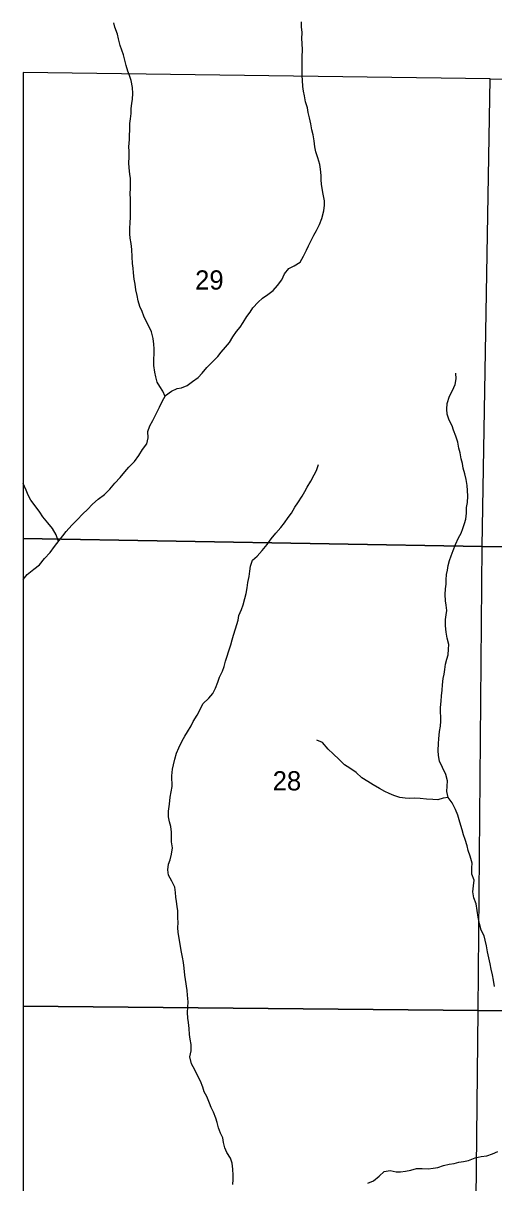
# Model space of a CAD drawing. Extents: x -10 to 158, y 8 to 33.
# Drawn here: x 24.6 to 25.627, y 16.093 to 18.62 of the extents above; entities that cross this region are included whole.
import ezdxf

# ---------------------------------------------------------------- set-up
doc = ezdxf.new("R2010")
doc.units = 0
for name, color, linetype in [('GM_X_Corporation', 7, 'Continuous'), ('GM_X_Minor_River', 7, 'Continuous'), ('GM_X_Section_Text', 7, 'Continuous')]:
    doc.layers.add(name, color=color, linetype=linetype)

msp = doc.modelspace()

# ---------------------------------------------------------------- linework, layer by layer
at = {"layer": 'GM_X_Corporation'}
for points in [[(24.6, 18.5128), (24.6, 17.4969), (25.6011, 17.4797), (25.6188, 18.4989)], [(25.6188, 18.4989), (26.6319, 18.4884), (26.6176, 17.4733), (25.6011, 17.4797)], [(24.6, 17.4969), (24.6, 16.4774), (25.5928, 16.4681), (25.6011, 17.4797)], [(25.6011, 17.4797), (26.6176, 17.4733), (26.6025, 16.4586), (25.5928, 16.4681)], [(24.6, 16.4774), (24.6, 15.4569), (25.5813, 15.4398), (25.5928, 16.4681)], [(26.6025, 16.4586), (26.5887, 15.4288), (25.5813, 15.4398), (25.5928, 16.4681)]]:
    msp.add_lwpolyline(points, close=True, dxfattribs=at)
at = {"layer": 'GM_X_Minor_River'}
for points in [[(24.9097, 17.8068), (24.9044, 17.8182), (24.8979, 17.828), (24.8926, 17.8379), (24.8891, 17.8497), (24.8872, 17.8595), (24.8853, 17.874), (24.8848, 17.8865), (24.8859, 17.9013), (24.8859, 17.9108), (24.8851, 17.9203), (24.8832, 17.9332), (24.8798, 17.9476), (24.8748, 17.9586), (24.8679, 17.9719), (24.863, 17.9818), (24.8595, 17.992), (24.8546, 18.0026), (24.8508, 18.0152), (24.8484, 18.0269), (24.8461, 18.0391), (24.8442, 18.0516), (24.8423, 18.0626), (24.8407, 18.0759), (24.8396, 18.0865), (24.8388, 18.0968), (24.838, 18.1112), (24.8372, 18.1272), (24.8356, 18.1401), (24.8333, 18.1515), (24.8325, 18.1613), (24.8325, 18.1739), (24.8336, 18.1845), (24.834, 18.1982), (24.8343, 18.213), (24.8343, 18.2248), (24.8339, 18.2362), (24.8335, 18.2499), (24.8338, 18.2594), (24.8342, 18.2715), (24.8338, 18.2814), (24.8326, 18.2913), (24.831, 18.3049), (24.8306, 18.3156), (24.831, 18.3285), (24.831, 18.341), (24.8306, 18.3509), (24.8317, 18.3665), (24.832, 18.3764), (24.8324, 18.387), (24.8327, 18.4014), (24.8342, 18.4121), (24.8353, 18.4235), (24.8357, 18.4341), (24.8368, 18.4451), (24.8383, 18.4546), (24.8394, 18.4672), (24.8386, 18.4801), (24.8355, 18.4953), (24.8321, 18.5059), (24.8282, 18.5154), (24.8248, 18.5283), (24.8221, 18.5397), (24.8187, 18.551), (24.8149, 18.5613), (24.8114, 18.5719), (24.8083, 18.5863), (24.8057, 18.5966), (24.8003, 18.6114), (24.7976, 18.6209)], [(25.1338, 18.029), (25.1452, 18.0378), (25.155, 18.0488), (25.1644, 18.061), (25.1701, 18.0736), (25.1792, 18.0858), (25.1913, 18.0915), (25.2042, 18.0995), (25.2118, 18.1125), (25.2178, 18.1258), (25.2223, 18.1353), (25.2284, 18.1463), (25.2344, 18.1585), (25.2401, 18.1684), (25.2465, 18.1817), (25.2518, 18.1947), (25.2559, 18.211), (25.2574, 18.2239), (25.257, 18.2334), (25.2543, 18.2475), (25.252, 18.2596), (25.2508, 18.2691), (25.25, 18.2786), (25.25, 18.2885), (25.2488, 18.3018), (25.2469, 18.312), (25.2431, 18.3265), (25.2385, 18.3401), (25.2362, 18.3511), (25.235, 18.364), (25.2327, 18.3766), (25.2297, 18.3876), (25.2273, 18.4012), (25.2247, 18.4141), (25.2216, 18.4259), (25.2204, 18.4358), (25.2162, 18.4487), (25.2135, 18.462), (25.2112, 18.4722), (25.2097, 18.4821), (25.2093, 18.4961), (25.2089, 18.5056), (25.2088, 18.5337), (25.2084, 18.5478), (25.2091, 18.5615), (25.2087, 18.577), (25.2075, 18.5865), (25.2086, 18.6002), (25.2071, 18.6124), (25.2074, 18.623)], [(24.6, 17.408), (24.609, 17.4183), (24.623, 17.4305), (24.6359, 17.4393), (24.6465, 17.4534), (24.6586, 17.4667), (24.6684, 17.4793), (24.6787, 17.4926), (24.6866, 17.5029), (24.6938, 17.5124), (24.7059, 17.5262), (24.718, 17.538), (24.7305, 17.5505), (24.7403, 17.5601), (24.7513, 17.5719), (24.7634, 17.5826), (24.7771, 17.5932), (24.7888, 17.6047), (24.8001, 17.6173), (24.8115, 17.6302), (24.8217, 17.642), (24.8308, 17.6527), (24.8425, 17.6645), (24.852, 17.6778), (24.8603, 17.6912), (24.8698, 17.7033), (24.8724, 17.7166), (24.872, 17.7299), (24.8761, 17.7429), (24.8829, 17.7539), (24.8897, 17.7676), (24.8973, 17.7836), (24.9029, 17.7958), (24.9108, 17.8087), (24.9237, 17.8179), (24.9362, 17.824), (24.9457, 17.8252), (24.9575, 17.8305), (24.9692, 17.8393), (24.9817, 17.8477), (24.9904, 17.8572), (25.0006, 17.8698), (25.0249, 17.8934), (25.0317, 17.9029), (25.0411, 17.914), (25.0502, 17.9243), (25.0574, 17.9365), (25.0653, 17.9479), (25.0733, 17.9578), (25.0801, 17.9681), (25.088, 17.981), (25.0948, 17.9905), (25.1012, 18), (25.1126, 18.0119), (25.1224, 18.0206), (25.1338, 18.029)], [(25.5224, 17.3975), (25.5228, 17.407), (25.5235, 17.4184), (25.5254, 17.4279), (25.5272, 17.4382), (25.5299, 17.4492), (25.5336, 17.4591), (25.5378, 17.4712), (25.5434, 17.4842), (25.5499, 17.4986), (25.5555, 17.5089), (25.5593, 17.5188), (25.5627, 17.5294), (25.5657, 17.5393), (25.5672, 17.5519), (25.5672, 17.5648), (25.5694, 17.5758), (25.5701, 17.5891), (25.569, 17.602), (25.5686, 17.6126), (25.5666, 17.6255), (25.5632, 17.6381), (25.5601, 17.6502), (25.5582, 17.6605), (25.5555, 17.6707), (25.5536, 17.684), (25.5505, 17.6939), (25.5478, 17.7071), (25.544, 17.7204), (25.5387, 17.7329), (25.5356, 17.7424), (25.5291, 17.7546), (25.5249, 17.7682), (25.5245, 17.7789), (25.5249, 17.7914), (25.5301, 17.807), (25.5362, 17.8199), (25.5422, 17.8325), (25.5448, 17.845), (25.544, 17.8576)], [(24.971, 17.0982), (24.9797, 17.1119), (24.9865, 17.126), (24.9918, 17.1363), (25.0047, 17.1489), (25.0138, 17.1592), (25.0198, 17.171), (25.0243, 17.1839), (25.0285, 17.1945), (25.0349, 17.2075), (25.0387, 17.2181), (25.0417, 17.2295), (25.0447, 17.2402), (25.0481, 17.25), (25.053, 17.2649), (25.0556, 17.2759), (25.0586, 17.2865), (25.0631, 17.2998), (25.0661, 17.3094), (25.0688, 17.3189), (25.0706, 17.3291), (25.0759, 17.3421), (25.0797, 17.3527), (25.0835, 17.3664), (25.0865, 17.377), (25.0887, 17.3896), (25.0902, 17.401), (25.0928, 17.4139), (25.0943, 17.4257), (25.0958, 17.4367), (25.0999, 17.4496), (25.1102, 17.4584), (25.1215, 17.471), (25.1321, 17.4843), (25.1412, 17.4965), (25.1514, 17.509), (25.1624, 17.5212), (25.1699, 17.5311), (25.1783, 17.5429), (25.1851, 17.5525), (25.1923, 17.565), (25.1991, 17.5745), (25.2085, 17.589), (25.2142, 17.5997), (25.2198, 17.6092), (25.2274, 17.6221), (25.235, 17.6358), (25.2395, 17.6453), (25.2444, 17.6583)], [(24.6772, 17.4908), (24.6718, 17.5051), (24.6642, 17.5188), (24.6535, 17.5313), (24.6432, 17.5446), (24.6364, 17.5544), (24.6265, 17.568), (24.6166, 17.5806), (24.6112, 17.5912), (24.6067, 17.6025), (24.6002, 17.6166), (24.6, 17.6169)], [(25.6281, 16.5206), (25.6258, 16.5343), (25.6235, 16.5457), (25.6208, 16.5582), (25.6189, 16.5696), (25.6158, 16.5829), (25.6131, 16.5958), (25.6104, 16.609), (25.6081, 16.6216), (25.6054, 16.631), (25.5993, 16.6432), (25.5951, 16.6568), (25.5924, 16.6713), (25.5905, 16.6864), (25.5878, 16.7005), (25.5832, 16.7141), (25.5809, 16.7266), (25.5824, 16.7396), (25.5839, 16.7525), (25.5786, 16.765), (25.5785, 16.779), (25.5793, 16.7893), (25.5754, 16.8045), (25.5709, 16.817), (25.5682, 16.8269), (25.564, 16.8409), (25.5605, 16.8511), (25.5578, 16.8618), (25.5548, 16.8716), (25.551, 16.8838), (25.5479, 16.894), (25.5433, 16.9065), (25.5357, 16.9205), (25.5273, 16.9323), (25.5243, 16.9452), (25.525, 16.957), (25.5253, 16.9691), (25.5219, 16.9828), (25.5146, 16.9979), (25.5085, 17.012), (25.5059, 17.0241), (25.5055, 17.0347), (25.5062, 17.0499), (25.5065, 17.0606), (25.508, 17.0765), (25.5103, 17.0883), (25.5114, 17.0989), (25.511, 17.1084), (25.5102, 17.1187), (25.5105, 17.1289), (25.5116, 17.1426), (25.5124, 17.1544), (25.5142, 17.1666), (25.515, 17.1783), (25.5165, 17.1916), (25.518, 17.2015), (25.5198, 17.2118), (25.5213, 17.2228), (25.5239, 17.2338), (25.527, 17.2433), (25.5281, 17.2555), (25.5288, 17.2657), (25.525, 17.2801), (25.523, 17.2931), (25.5215, 17.3067), (25.5215, 17.3208), (25.5226, 17.3303), (25.5241, 17.3398), (25.5225, 17.3519), (25.5214, 17.3614), (25.5206, 17.3751), (25.5213, 17.3876), (25.5224, 17.3975)], [(25.0576, 16.0889), (25.058, 16.0995), (25.0579, 16.109), (25.0575, 16.1223), (25.0556, 16.1352), (25.0525, 16.1462), (25.0442, 16.1587), (25.04, 16.1686), (25.0373, 16.1803), (25.0354, 16.1906), (25.0304, 16.2008), (25.0258, 16.2122), (25.0231, 16.2243), (25.0205, 16.2338), (25.0151, 16.2467), (25.0098, 16.2566), (25.0064, 16.2664), (25.0003, 16.2808), (24.9949, 16.291), (24.9919, 16.3013), (24.9865, 16.3138), (24.9785, 16.3297), (24.9743, 16.3392), (24.9671, 16.3521), (24.9636, 16.3673), (24.9663, 16.3806), (24.9662, 16.3938), (24.9643, 16.406), (24.9628, 16.4162), (24.962, 16.4288), (24.9604, 16.4417), (24.9593, 16.4512), (24.9585, 16.4637), (24.9592, 16.4758), (24.9596, 16.4872), (24.9588, 16.5013), (24.9576, 16.5119), (24.9541, 16.5358), (24.953, 16.5453), (24.9514, 16.5601), (24.9495, 16.573), (24.9472, 16.5844), (24.9449, 16.5988), (24.9426, 16.6128), (24.9406, 16.6254), (24.9383, 16.6386), (24.9376, 16.6485), (24.9379, 16.6599), (24.9375, 16.6705), (24.9371, 16.6853), (24.9359, 16.6948), (24.9344, 16.7058), (24.9329, 16.7153), (24.9321, 16.7256), (24.9305, 16.737), (24.9244, 16.7499), (24.9172, 16.7635), (24.9156, 16.7749), (24.9167, 16.787), (24.9205, 16.7969), (24.9235, 16.8091), (24.9254, 16.8228), (24.9238, 16.8357), (24.9238, 16.8459), (24.9234, 16.8569), (24.9219, 16.8695), (24.9192, 16.8793), (24.9173, 16.89), (24.9169, 16.9029), (24.9195, 16.9181), (24.921, 16.9329), (24.9228, 16.9447), (24.9247, 16.9564), (24.9246, 16.98), (24.9257, 16.994), (24.928, 17.0035), (24.9306, 17.0157), (24.9344, 17.029), (24.9397, 17.0404), (24.9468, 17.056), (24.9525, 17.0663), (24.9582, 17.0758), (24.9665, 17.0887), (24.971, 17.0982)], [(25.5273, 16.9323), (25.5163, 16.9311), (25.5042, 16.9273), (25.4939, 16.928), (25.4795, 16.9287), (25.4659, 16.9306), (25.453, 16.9309), (25.4431, 16.9305), (25.4336, 16.9312), (25.4215, 16.9327), (25.4085, 16.9368), (25.3987, 16.941), (25.3888, 16.9459), (25.3774, 16.9519), (25.3633, 16.9602), (25.3516, 16.967), (25.3386, 16.9753), (25.3261, 16.987), (25.3124, 16.9965), (25.301, 17.004), (25.2892, 17.0154), (25.2763, 17.0275), (25.2652, 17.0381), (25.2527, 17.0521), (25.2409, 17.0578)], [(25.3517, 16.0918), (25.3642, 16.0968), (25.3767, 16.1071), (25.3877, 16.117), (25.4002, 16.1193), (25.4135, 16.1163), (25.4233, 16.1167), (25.4343, 16.1183), (25.4457, 16.1202), (25.4582, 16.1237), (25.47, 16.1241), (25.4837, 16.1234), (25.4943, 16.1242), (25.5045, 16.1261), (25.517, 16.1303), (25.5295, 16.133), (25.5405, 16.135), (25.55, 16.1373), (25.5607, 16.1392), (25.5713, 16.1415), (25.5861, 16.1469), (25.5993, 16.15), (25.6111, 16.1515), (25.624, 16.1554), (25.6357, 16.1611)]]:
    msp.add_lwpolyline(points, dxfattribs=at)

# ---------------------------------------------------------------- texts
at = {"layer": 'GM_X_Section_Text'}
for s, p in [('29', (24.975, 18.0396)), ('28', (25.1442, 16.9479))]:
    msp.add_text(s, height=0.04186, rotation=0, dxfattribs=at).set_placement(p)

doc.saveas('drawing.dxf')
